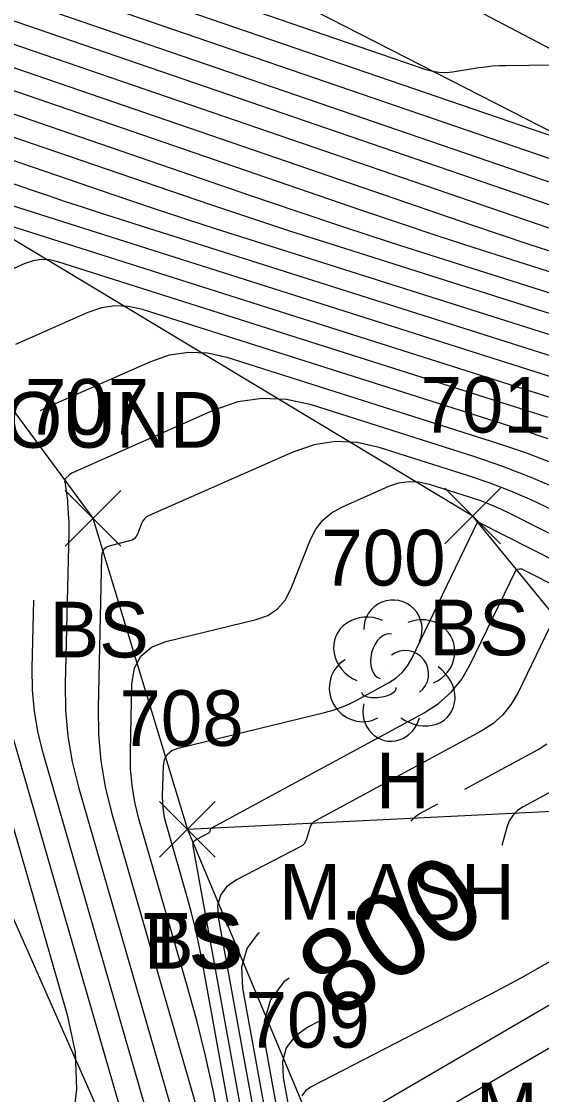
# Model space of a CAD drawing. Extents: x 1650836 to 1652450, y 332578 to 333908.
# Drawn here: x 1652038.33 to 1652057.01, y 332763.95 to 332802.49 of the extents above; entities that cross this region are included whole.
import ezdxf

# ---------------------------------------------------------------- set-up
doc = ezdxf.new("R2010")
doc.units = 0
for name, color, linetype in [('L_A', 7, 'Continuous'), ('L_C', 7, 'Continuous'), ('L_I', 7, 'Continuous'), ('L_TIC', 7, 'Continuous'), ('LELB', 7, 'Continuous'), ('LSOGCMA', 7, 'Continuous'), ('LSOGCMA_T', 7, 'Continuous'), ('LSOGCMI', 7, 'Continuous'), ('LTD', 7, 'Continuous'), ('M_C', 7, 'Continuous'), ('RGR', 7, 'Continuous')]:
    doc.layers.add(name, color=color, linetype=linetype)

msp = doc.modelspace()

# ---------------------------------------------------------------- linework, layer by layer
at = {"layer": 'L_TIC'}
for points in [[(1652039.892, 332783.647), (1652041.892, 332785.647)], [(1652041.892, 332783.647), (1652039.892, 332785.647)], [(1652053.537, 332783.724), (1652055.537, 332785.724)], [(1652055.537, 332783.724), (1652053.537, 332785.724)], [(1652043.285, 332772.47), (1652045.285, 332774.47)], [(1652045.285, 332772.47), (1652043.285, 332774.47)], [(1652043.285, 332772.47), (1652045.285, 332774.47)], [(1652045.285, 332772.47), (1652043.285, 332774.47)]]:
    msp.add_lwpolyline(points, dxfattribs=at)
at = {"layer": 'LELB'}
for points in [[(1651844.759, 332915.941), (1651880.379, 332894.976), (1651917.082, 332874.787), (1651949.824, 332853.945), (1651967.074, 332844.342), (1652000.53, 332828.254), (1652035.357, 332809.776), (1652067.23, 332793.489), (1652106.029, 332773.108), (1652143.274, 332753.324), (1652172.167, 332734.049)], [(1652048.756, 332662.461), (1652082.555, 332678.298), (1652130.366, 332703.201), (1652148.083, 332715.406), (1652159.47, 332726.367), (1652148.02, 332734.227), (1652128.413, 332739.339), (1652116.951, 332747.33), (1652106.793, 332756.875), (1652094.604, 332761.138), (1652083.802, 332764.466), (1652074.482, 332770.284), (1652065.17, 332770.428), (1652062.989, 332774.387), (1652054.537, 332784.724), (1652034.993, 332796.475), (1652025.062, 332801.1), (1652009.772, 332808.074), (1651988.967, 332816.401), (1651980.006, 332832.954), (1651960.575, 332843.477), (1651932.852, 332862.75), (1651890.753, 332886.019), (1651847.527, 332911.35)], [(1652023.947, 332796.746), (1652033.145, 332795.123), (1652040.892, 332784.647), (1652044.285, 332773.47), (1652048.825, 332762.633), (1652060.903, 332762.254), (1652066.549, 332756.035)], [(1652046.201, 332751.794), (1652032.797, 332782.109), (1652031.244, 332792.189)], [(1652076.167, 332772.779), (1652062.989, 332774.387), (1652044.285, 332773.47)]]:
    msp.add_lwpolyline(points, dxfattribs=at)
at = {"layer": 'LSOGCMA'}
for points in [[(1652062.441, 332794.127), (1652036.56, 332803.009)], [(1652057.246, 332788.263), (1652039.633, 332793.856), (1652039.333, 332793.924), (1652039.036, 332793.936), (1652038.742, 332793.892), (1652038.451, 332793.792), (1652037.088, 332793.19)], [(1652036.584, 332778.551), (1652039.972, 332766.816), (1652040.25, 332765.477), (1652040.308, 332764.146), (1652040.148, 332762.823), (1652039.767, 332761.509), (1652037.169, 332754.567)], [(1652058.937, 332775.687), (1652056.345, 332774.283), (1652056.139, 332774.146), (1652055.973, 332773.977), (1652055.847, 332773.776), (1652055.761, 332773.544), (1652055.587, 332772.895)], [(1652047.948, 332768.131), (1652047.749, 332767.992), (1652047.268, 332767.346), (1652047.05, 332766.571), (1652047.094, 332765.667), (1652048.02, 332760.574)]]:
    msp.add_lwpolyline(points, dxfattribs=at)
at = {"layer": 'LSOGCMI'}
for points in [[(1652058.221, 332800.931), (1652055.722, 332800.9), (1652055.48, 332800.893), (1652055.24, 332800.877), (1652055, 332800.852), (1652054.76, 332800.819), (1652053.805, 332800.669), (1652053.567, 332800.646), (1652053.332, 332800.652), (1652053.099, 332800.687), (1652052.869, 332800.751), (1652035.928, 332806.565)], [(1652058.008, 332798.153), (1652036.086, 332805.676)], [(1652063.146, 332795.555), (1652036.244, 332804.787)], [(1652036.402, 332803.898), (1652066.415, 332793.598)], [(1652058.468, 332794.656), (1652036.718, 332802.12)], [(1652036.876, 332801.231), (1652054.495, 332795.185), (1652055.525, 332794.834), (1652056.557, 332794.49), (1652057.591, 332794.152), (1652058.627, 332793.82), (1652064.374, 332791.995), (1652064.609, 332791.915), (1652064.84, 332791.826), (1652065.068, 332791.728), (1652065.291, 332791.62), (1652066.178, 332791.172), (1652066.401, 332791.062), (1652066.626, 332790.957), (1652066.854, 332790.858), (1652067.083, 332790.763), (1652072.368, 332788.644), (1652073.329, 332788.27), (1652074.297, 332787.917), (1652075.273, 332787.584), (1652076.256, 332787.272), (1652082.321, 332785.415)], [(1652063.483, 332791.528), (1652055.942, 332793.923), (1652054.583, 332794.359), (1652053.227, 332794.803), (1652051.873, 332795.254), (1652050.521, 332795.714), (1652037.034, 332800.342)], [(1652037.192, 332799.453), (1652046.548, 332796.242), (1652048.221, 332795.674), (1652049.897, 332795.115), (1652051.576, 332794.566), (1652053.258, 332794.026), (1652062.592, 332791.062)], [(1652061.701, 332790.595), (1652049.453, 332794.485), (1652048.007, 332794.949), (1652046.564, 332795.421), (1652045.124, 332795.901), (1652043.687, 332796.389), (1652037.35, 332798.564)], [(1652037.094, 332797.817), (1652041.183, 332796.414), (1652042.206, 332796.066), (1652043.231, 332795.724), (1652044.259, 332795.388), (1652045.288, 332795.058), (1652060.81, 332790.129)], [(1652036.244, 332797.274), (1652038.679, 332796.439), (1652039.288, 332796.232), (1652039.899, 332796.028), (1652040.51, 332795.828), (1652041.123, 332795.631), (1652059.919, 332789.663)], [(1652036.958, 332796.205), (1652059.028, 332789.196), (1652059.703, 332788.967), (1652060.367, 332788.711), (1652061.02, 332788.429), (1652061.662, 332788.121), (1652064.21, 332786.833), (1652064.85, 332786.518), (1652065.496, 332786.218), (1652066.149, 332785.931), (1652066.808, 332785.658), (1652071.714, 332783.691), (1652072.145, 332783.536), (1652072.583, 332783.414), (1652073.029, 332783.323), (1652073.483, 332783.265), (1652075.314, 332783.097), (1652075.769, 332783.041), (1652076.217, 332782.956), (1652076.659, 332782.843), (1652077.094, 332782.701), (1652103.425, 332773.197)], [(1652036.597, 332795.57), (1652058.137, 332788.73), (1652058.885, 332788.476), (1652059.621, 332788.192), (1652060.345, 332787.879), (1652061.057, 332787.537), (1652063.881, 332786.11), (1652064.591, 332785.761), (1652065.308, 332785.428), (1652066.031, 332785.11), (1652066.762, 332784.808), (1652070.826, 332783.178), (1652071.341, 332782.993), (1652071.865, 332782.846), (1652072.398, 332782.738), (1652072.941, 332782.669), (1652075.131, 332782.468), (1652075.674, 332782.401), (1652076.21, 332782.299), (1652076.739, 332782.164), (1652077.26, 332781.994), (1652101.446, 332773.264)], [(1652057.249, 332787.493), (1652056.355, 332787.797), (1652042.669, 332792.143), (1652042.172, 332792.255), (1652041.681, 332792.275), (1652041.195, 332792.202), (1652040.713, 332792.037), (1652038.113, 332790.887)], [(1652039.005, 332788.513), (1652039.055, 332788.544), (1652039.138, 332788.585), (1652042.976, 332790.281), (1652043.647, 332790.512), (1652044.326, 332790.614), (1652045.012, 332790.586), (1652045.705, 332790.43), (1652055.464, 332787.331), (1652056.432, 332787.002), (1652057.384, 332786.635)], [(1652057.646, 332785.681), (1652056.638, 332786.116), (1652055.614, 332786.511), (1652054.573, 332786.864), (1652048.741, 332788.716), (1652047.851, 332788.917), (1652046.971, 332788.952), (1652046.1, 332788.822), (1652045.238, 332788.526), (1652040.164, 332786.283), (1652040.129, 332786.265), (1652040.096, 332786.245), (1652040.065, 332786.223), (1652040.035, 332786.197), (1652039.922, 332786.089), (1652039.898, 332786.061), (1652039.883, 332786.029), (1652039.876, 332785.995), (1652039.878, 332785.958), (1652039.946, 332785.533), (1652039.958, 332785.449), (1652039.969, 332785.365), (1652039.977, 332785.281), (1652039.983, 332785.196), (1652040.019, 332784.625), (1652040.025, 332784.501), (1652040.029, 332784.378), (1652040.03, 332784.254), (1652040.028, 332784.13), (1652039.898, 332778.697), (1652039.911, 332777.755), (1652039.996, 332776.822), (1652040.151, 332775.898), (1652040.379, 332774.984), (1652045.577, 332756.979)], [(1652057.411, 332784.935), (1652056.664, 332785.294), (1652055.903, 332785.623), (1652055.13, 332785.92), (1652054.345, 332786.187), (1652051.178, 332787.193), (1652050.39, 332787.371), (1652049.61, 332787.402), (1652048.838, 332787.287), (1652048.075, 332787.024), (1652042.911, 332784.741), (1652042.822, 332784.692), (1652042.748, 332784.629), (1652042.688, 332784.553), (1652042.643, 332784.463), (1652042.49, 332784.074), (1652042.443, 332783.986), (1652042.381, 332783.916), (1652042.303, 332783.864), (1652042.21, 332783.83), (1652041.514, 332783.66), (1652041.382, 332783.609), (1652041.287, 332783.529), (1652041.228, 332783.419), (1652041.206, 332783.279), (1652041.076, 332777.835), (1652041.089, 332776.881), (1652041.175, 332775.937), (1652041.332, 332775.001), (1652041.562, 332774.075), (1652044.917, 332762.455)], [(1652045.454, 332762.873), (1652045.213, 332764.108), (1652044.941, 332765.337), (1652044.638, 332766.558), (1652044.304, 332767.772), (1652042.547, 332773.856), (1652042.4, 332774.448), (1652042.3, 332775.045), (1652042.245, 332775.648), (1652042.237, 332776.256), (1652042.295, 332778.704), (1652042.383, 332779.258), (1652042.615, 332779.694), (1652042.992, 332780.014), (1652043.514, 332780.218), (1652046.762, 332781.008), (1652047.179, 332781.158), (1652047.526, 332781.39), (1652047.802, 332781.701), (1652048.008, 332782.094), (1652048.713, 332783.879), (1652048.903, 332784.257), (1652049.154, 332784.578), (1652049.464, 332784.841), (1652049.834, 332785.046), (1652051.528, 332785.795), (1652051.883, 332785.917), (1652052.243, 332785.971), (1652052.606, 332785.957), (1652052.973, 332785.874), (1652054.448, 332785.405), (1652054.814, 332785.281), (1652055.173, 332785.142), (1652055.528, 332784.989), (1652055.876, 332784.822), (1652063.346, 332781.047)], [(1652046.948, 332757.019), (1652044.791, 332768.878), (1652044.687, 332769.413), (1652044.569, 332769.946), (1652044.438, 332770.475), (1652044.293, 332771.001), (1652043.532, 332773.638), (1652043.468, 332773.894), (1652043.425, 332774.152), (1652043.401, 332774.414), (1652043.398, 332774.678), (1652043.423, 332775.738), (1652043.461, 332775.978), (1652043.561, 332776.167), (1652043.725, 332776.306), (1652043.951, 332776.394), (1652049.215, 332777.675), (1652049.521, 332777.76), (1652049.819, 332777.864), (1652050.111, 332777.987), (1652050.394, 332778.129), (1652051.515, 332778.736), (1652051.777, 332778.904), (1652052.004, 332779.106), (1652052.196, 332779.343), (1652052.352, 332779.612), (1652054.713, 332784.502), (1652054.714, 332784.504), (1652054.716, 332784.505), (1652054.718, 332784.506), (1652054.72, 332784.507), (1652054.73, 332784.509), (1652054.735, 332784.509), (1652054.74, 332784.507), (1652063.284, 332780.189)], [(1652047.141, 332758.321), (1652044.495, 332772.87), (1652044.491, 332772.951), (1652044.511, 332773.021), (1652044.554, 332773.078), (1652044.621, 332773.125), (1652045.058, 332773.35), (1652045.073, 332773.36), (1652045.085, 332773.372), (1652045.094, 332773.387), (1652045.1, 332773.404), (1652045.12, 332773.476), (1652045.126, 332773.492), (1652045.135, 332773.507), (1652045.147, 332773.519), (1652045.162, 332773.529), (1652052.789, 332777.659), (1652053.31, 332777.993), (1652053.76, 332778.395), (1652054.14, 332778.863), (1652054.45, 332779.399), (1652056.08, 332782.773), (1652056.091, 332782.791), (1652056.106, 332782.805), (1652056.123, 332782.815), (1652056.144, 332782.82), (1652056.232, 332782.835), (1652056.254, 332782.836), (1652056.276, 332782.835), (1652056.296, 332782.83), (1652056.317, 332782.821), (1652063.222, 332779.332)], [(1652046.04, 332752.184), (1652039.114, 332776.173), (1652038.924, 332776.934), (1652038.795, 332777.704), (1652038.724, 332778.481), (1652038.714, 332779.266), (1652038.772, 332781.7)], [(1652057.447, 332781.044), (1652056.166, 332778.392), (1652055.918, 332777.964), (1652055.614, 332777.59), (1652055.255, 332777.269), (1652054.838, 332777.002), (1652048.89, 332773.781), (1652048.811, 332773.728), (1652048.748, 332773.664), (1652048.7, 332773.587), (1652048.667, 332773.498), (1652048.565, 332773.12), (1652048.532, 332773.032), (1652048.484, 332772.956), (1652048.42, 332772.892), (1652048.341, 332772.841), (1652046.046, 332771.656), (1652045.696, 332771.413), (1652045.47, 332771.109), (1652045.368, 332770.745), (1652045.389, 332770.319), (1652047.434, 332759.072)], [(1652037.849, 332777.362), (1652043.006, 332759.5)], [(1652054.257, 332774.92), (1652056.888, 332776.344), (1652057.199, 332776.544)], [(1652052.325, 332773.763), (1652052.361, 332773.82), (1652052.475, 332773.937), (1652052.617, 332774.032), (1652053.287, 332774.395)], [(1652047.727, 332759.823), (1652046.282, 332767.769), (1652046.244, 332768.538), (1652046.43, 332769.198), (1652046.839, 332769.747), (1652046.872, 332769.77)], [(1652057.407, 332768.777), (1652056.852, 332768.459), (1652056.294, 332768.147), (1652055.731, 332767.843), (1652055.164, 332767.545), (1652048.735, 332764.224), (1652048.533, 332764.084), (1652048.403, 332763.909)], [(1652051.324, 332763.692), (1652060.292, 332768.917)], [(1652053.426, 332763.377), (1652060, 332767.207)], [(1652048.982, 332766.557), (1652048.613, 332766.366), (1652048.141, 332766.038), (1652047.835, 332765.628), (1652047.697, 332765.135), (1652047.725, 332764.561), (1652048.314, 332761.325)]]:
    msp.add_lwpolyline(points, dxfattribs=at)
at = {"layer": 'LTD'}
msp.add_line((1652051.624, 332779.231), (1652051.624, 332779.231), dxfattribs=at)
msp.add_line((1652051.624, 332779.231), (1652051.624, 332779.231), dxfattribs=at)
msp.add_arc((1652051.671, 332780.665), 1.047, 335.5272, 180.9563, dxfattribs=at)
for centre, major_axis, ratio, start_param, end_param in [((1652050.832, 332779.897), (1.21, -0.512), 0.895232, 1.570796, 4.712389), ((1652052.666, 332779.814), (-1.141, -0.483), 0.949671, 1.570796, 4.712389), ((1652051.416, 332779.689), (-0.208, -0.792), 0.645439, 3.141593, 6.283185), ((1652052.124, 332779.064), (-0.5, 0.667), 0.989748, 3.141593, 6.283185), ((1652050.541, 332778.522), (0.584, -1.042), 0.959034, 3.141593, 6.283185), ((1652052.624, 332778.398), (-1.09, 0.792), 0.841452, 1.570796, 4.712389), ((1652051.166, 332778.481), (-0.625, -0.083), 0.423636, 0, 3.141593), ((1652051.625, 332777.731), (0.265, 1.061), 0.942809, 1.570796, 4.712389)]:
    msp.add_ellipse(centre, major_axis=major_axis, ratio=ratio, start_param=start_param, end_param=end_param, dxfattribs=at)
at = {"layer": 'RGR'}
msp.add_lwpolyline([(1651963.926, 332842.71), (1651967.074, 332844.342), (1651975.028, 332844.451), (1652001.752, 332830.477), (1652036.76, 332812.304), (1652068.698, 332795.548), (1652107.135, 332775.504), (1652144.421, 332755.8), (1652165.98, 332744.268), (1652170.761, 332738.792), (1652172.167, 332734.049)], dxfattribs=at)

# ---------------------------------------------------------------- texts
at = {"layer": 'L_A'}
for s, p in [('BS', (1652052.978, 332779.724)), ('BS', (1652039.333, 332779.647)), ('H', (1652051.057, 332774.231)), ('TS', (1652042.695, 332768.47)), ('BS', (1652042.726, 332768.47))]:
    msp.add_text(s, height=2, dxfattribs=at).set_placement(p)
at = {"layer": 'L_C'}
for s, p in [('M.ASH', (1652047.577, 332770.231)), ('M.MAPLE', (1652054.649, 332762.377))]:
    msp.add_text(s, height=2, dxfattribs=at).set_placement(p)
at = {"layer": 'L_I'}
for s, p in [('707', (1652038.451, 332787.647)), ('701', (1652052.663, 332787.724)), ('700', (1652049.097, 332782.231)), ('708', (1652041.844, 332776.47)), ('708', (1652041.844, 332776.47)), ('709', (1652046.376, 332765.633))]:
    msp.add_text(s, height=2, dxfattribs=at).set_placement(p)
at = {"layer": 'LSOGCMA_T'}
msp.add_text('800', height=3, rotation=33.2891, dxfattribs=at).set_placement((1652049.607, 332766.595))
at = {"layer": 'M_C'}
msp.add_text('EXPOSED REBAR ONLY... BOUND', height=2, dxfattribs=at).set_placement((1652002.042, 332787.179))

doc.saveas('drawing.dxf')
